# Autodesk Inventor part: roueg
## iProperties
Shininess: 69.0
Length Units: 11269
Angle Units: 11279
Time Units: 11290
Mass Units: 11283
Length Display Precision: 3
Angle Display Precision: 2
Compacted: True
Created: 2001-12
Part Number: roueg
Material: Par défaut
Document SubType Name: Modélisation
Designer: pichon
Density: 0.0
Volumn: 0.0
Area: 0.0
PropertySet Name: Model Information
Control State: 0
Master: False
Checked Out: False
Author: pichon
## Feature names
1. Révolution1 [Revolution]
